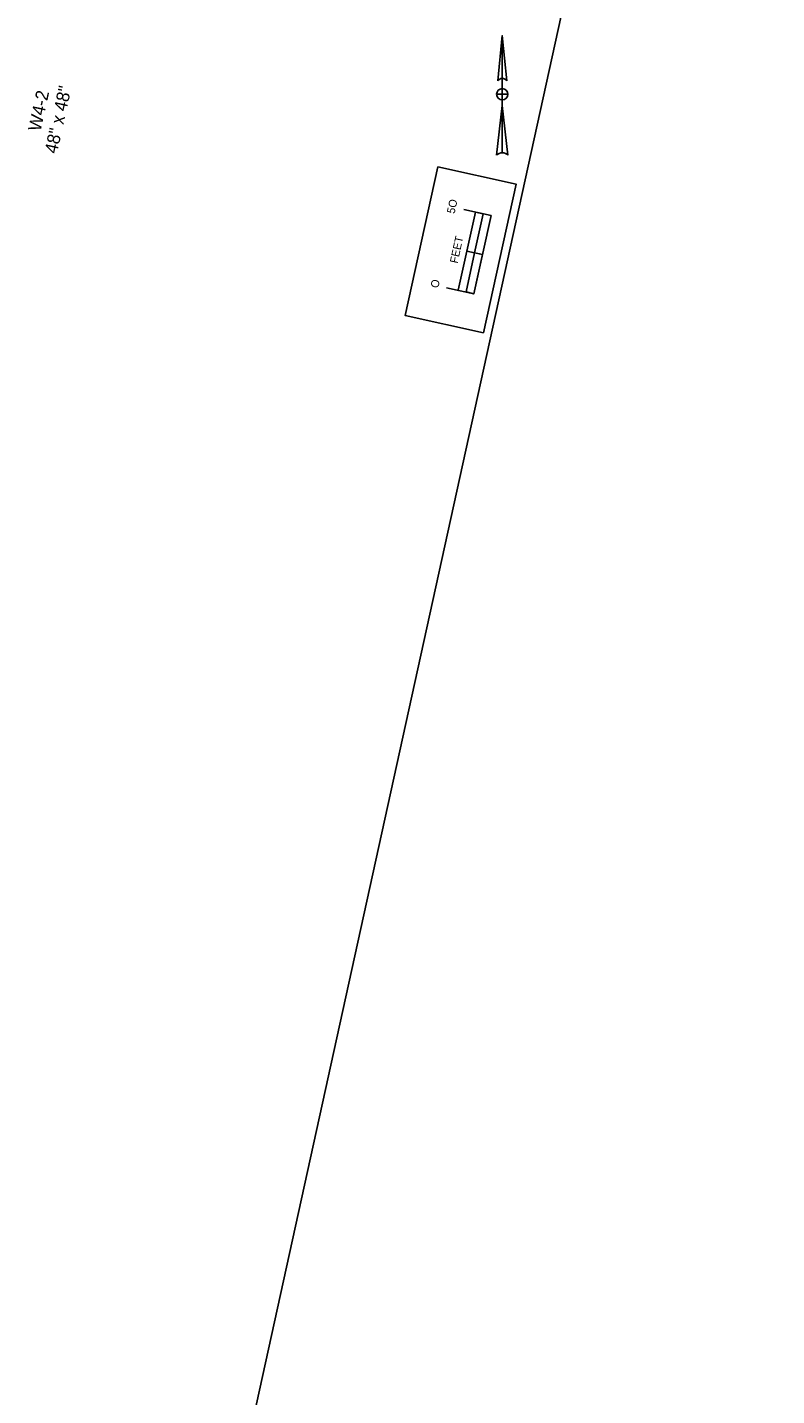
# Model space of a CAD drawing. Extents: x 14104283 to 14121738, y 8635219 to 8671666.
# Drawn here: x 14107780 to 14108248, y 8637146 to 8638001 of the extents above; entities that cross this region are included whole.
import ezdxf

# ---------------------------------------------------------------- set-up
doc = ezdxf.new("R2010")
doc.units = 0
for name, color, linetype in [('Cell', 7, 'Continuous'), ('dsnCellsNorthArrow', 7, 'Continuous'), ('dsnCellsScaleBlock', 7, 'Continuous'), ('dsnNonPlotable', 7, 'Continuous')]:
    doc.layers.add(name, color=color, linetype=linetype)

msp = doc.modelspace()

# ---------------------------------------------------------------- linework, layer by layer
at = {"layer": 'dsnCellsNorthArrow'}
for p, q in [((14108076.38, 8637995.68), (14108079.2, 8637967.51)), ((14108076.38, 8637995.68), (14108076.38, 8637922.44)), ((14108073.57, 8637967.51), (14108073.56, 8637967.51)), ((14108073.67, 8637967.78), (14108074.2, 8637968.36)), ((14108076.38, 8637955.54), (14108076.38, 8637955.54)), ((14108072.86, 8637921.03), (14108076.38, 8637952.02))]:
    msp.add_line(p, q, dxfattribs=at)
for points in [[(14108073.56, 8637967.51), (14108076.38, 8637995.68), (14108076.38, 8637968.92)], [(14108076.38, 8637955.54), (14108076.38, 8637959.06), (14108072.86, 8637959.06)], [(14108079.9, 8637959.06), (14108076.38, 8637959.06), (14108076.38, 8637962.59)], [(14108076.38, 8637922.44), (14108076.38, 8637952.02), (14108079.9, 8637921.03)]]:
    msp.add_lwpolyline(points, dxfattribs=at)
for centre, radius, start, end in [((14108076.38, 8637965.4), 3.52, 90.02039, 143.12574), ((14108076.38, 8637965.4), 3.52, 36.84806, 90.02184), ((14108076.38, 8637959.06), 3.52, 90, 180), ((14108076.38, 8637959.06), 3.52, 180, 270), ((14108076.38, 8637959.06), 3.52, 0, 90), ((14108076.38, 8637959.06), 3.52, 270, 360), ((14108076.38, 8637917.34), 5.1, 89.98939, 133.61895), ((14108076.38, 8637917.33), 5.11, 46.40206, 90.00064)]:
    msp.add_arc(centre, radius, start, end, dxfattribs=at)
at = {"layer": 'dsnCellsScaleBlock'}
msp.add_line((14108064.01, 8637858.86), (14108054.24, 8637861.01), dxfattribs=at)
msp.add_line((14108064.01, 8637858.86), (14108054.24, 8637861.01), dxfattribs=at)
for points in [[(14108064.56, 8637810.11), (14108015.73, 8637820.84), (14108036.11, 8637913.63), (14108084.95, 8637902.9)], [(14108015.73, 8637820.84), (14108036.11, 8637913.63), (14108084.95, 8637902.9), (14108064.56, 8637810.11)], [(14108064.56, 8637810.11), (14108015.73, 8637820.84), (14108036.11, 8637913.63), (14108084.95, 8637902.9)], [(14108059.09, 8637859.94), (14108064.46, 8637884.36), (14108059.61, 8637885.43), (14108054.24, 8637861.01)], [(14108058.65, 8637834.45), (14108064.01, 8637858.86), (14108059.09, 8637859.94), (14108053.73, 8637835.53)]]:
    msp.add_lwpolyline(points, close=True, dxfattribs=at)
for points in [[(14108041.55, 8637838.2), (14108058.65, 8637834.45), (14108069.38, 8637883.28), (14108052.28, 8637887.04)], [(14108048.88, 8637836.59), (14108059.61, 8637885.43)]]:
    msp.add_lwpolyline(points, dxfattribs=at)
at = {"layer": 'dsnNonPlotable'}
msp.add_lwpolyline([(14106924.98, 8637306.69), (14107261.36, 8638837.67), (14108247.83, 8638620.92), (14107911.44, 8637089.94)], close=True, dxfattribs=at)

# ---------------------------------------------------------------- texts
at = {"layer": 'Cell'}
for s, p in [('48" x 48"', (14107798.04, 8637921.53)), ('W4-2', (14107787.78, 8637935.44))]:
    msp.add_text(s, height=8, rotation=77.61021, dxfattribs=at).set_placement(p)
at = {"layer": 'dsnCellsScaleBlock'}
for s, p in [('5O', (14108046.52, 8637884.13)), ('FEET', (14108048.41, 8637853.1)), ('O', (14108036.32, 8637837.68))]:
    msp.add_text(s, height=5, rotation=77.60784, dxfattribs=at).set_placement(p)

doc.saveas('drawing.dxf')
